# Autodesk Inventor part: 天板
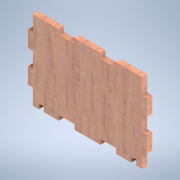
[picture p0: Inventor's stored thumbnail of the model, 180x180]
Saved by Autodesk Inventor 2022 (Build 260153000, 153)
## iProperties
Created: 2024-11
Part Number: 天板
Material: 木 (オーク)
Document SubType Name: Modeling
Designer: shimizu
Density: 0.76 g/cm^3
Appearance: ホワイト オーク材 - ナチュラル 標準の光沢
Author: shimizu
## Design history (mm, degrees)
sketch "スケッチ1"
  geometry: L1 (-25.119, 2.566)-(-27.619, 2.566); L2 (-27.619, 2.566)-(-27.619, -5.434); L3 (-27.619, -5.434)-(-25.119, -5.434); L4 (-25.119, -13.434)-(-27.619, -13.434); L5 (-27.619, -13.434)-(-27.619, -21.434); L6 (-27.619, -21.434)-(-25.119, -21.434); L7 (29.881, 2.566)-(32.381, 2.566); L8 (32.381, 2.566)-(32.381, -5.434); L9 (32.381, -5.434)-(29.881, -5.434); L10 (29.881, -13.434)-(32.381, -13.434); L11 (32.381, -13.434)-(32.381, -21.434); L12 (32.381, -21.434)-(29.881, -21.434); L13 (-25.119, 2.566)-(-25.119, 10.566); L14 (-25.119, -29.434)-(-25.119, -21.434); L15 (-25.119, -13.434)-(-25.119, -5.434); L16 (29.881, 10.566)-(29.881, 2.566); L17 (29.881, -5.434)-(29.881, -13.434); L18 (29.881, -21.434)-(29.881, -29.434); L19 (-4.119, -29.434)-(-4.119, -26.934); L20 (-4.119, -26.934)-(-12.119, -26.934); L21 (-12.119, -26.934)-(-12.119, -29.434); L22 (16.881, -29.434)-(16.881, -26.934); L23 (16.881, -26.934)-(8.881, -26.934); L24 (8.881, -26.934)-(8.881, -29.434); L25 (-4.119, 10.566)-(-4.119, 8.066); L26 (-4.119, 8.066)-(-12.119, 8.066); L27 (-12.119, 8.066)-(-12.119, 10.566); L28 (16.881, 10.566)-(16.881, 8.066); L29 (16.881, 8.066)-(8.881, 8.066); L30 (8.881, 8.066)-(8.881, 10.566); L31 (-25.119, 10.566)-(-12.119, 10.566); L32 (-4.119, 10.566)-(8.881, 10.566); L33 (16.881, 10.566)-(29.881, 10.566); L34 (-12.119, -29.434)-(-25.119, -29.434); L35 (29.881, -29.434)-(16.881, -29.434); L36 (8.881, -29.434)-(-4.119, -29.434); L37 (24.381, -29.434)-(26.881, -29.434); L38 (26.881, -29.434)-(26.881, -26.934); L39 (26.881, -26.934)-(24.381, -26.934); L40 (24.381, -26.934)-(24.381, -29.434); L41 (-22.119, -29.434)-(-19.619, -29.434); L42 (-19.619, -29.434)-(-19.619, -26.934); L43 (-19.619, -26.934)-(-22.119, -26.934); L44 (-22.119, -26.934)-(-22.119, -29.434); 3 further points
  constraints: 88 end point, 30 parallel, 15 perpendicular, 9 horizontal, 2 collinear, 2 point on line
  dimensions: "d29" = 55 distance between parallel lines of L17 L15; "d30" = 35 distance between parallel lines of L20 L26; "d31" = 60 distance between parallel lines of L11 L5; "d32" = 13 distance of L21.end L14.start; "d33" = 13 distance of L24.end L19.start; "d34" = 13 distance of L18.end L22.start; "d35" = 13 distance of L13.end L27.end; "d36" = 13 distance of L25.start L30.end; "d37" = 13 distance of L28.start L16.start; "d38" = 8 distance of L28.end L29.end; "d39" = 8 distance of L25.end L26.end; "d40" = 8 distance of L22.end L23.end; "d41" = 8 distance of L19.end L20.end; "d42" = 8 distance of L9.end L10.start; "d43" = 2.5 distance between parallel lines of L40 L38; "d44" = 2.5 distance between parallel lines of L37 L39; "d45" = 3 distance between parallel lines of L38 L18; "d46" = 2.5 distance of L43.end L41.start; "d47" = 2.5 distance of L42.end L43.end; "d48" = 3 distance between parallel lines of L44 L14
extrude "押し出し1" new body sketch "スケッチ1" distance "d2" = 2.5; taper "d3" = 0 deg
node "ソリッド1"
